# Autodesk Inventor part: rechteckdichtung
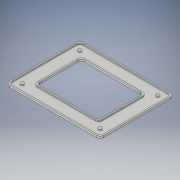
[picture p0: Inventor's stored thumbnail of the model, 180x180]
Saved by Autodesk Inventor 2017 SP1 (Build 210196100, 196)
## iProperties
Part Number: rechteckdichtung
Material: Generisch
Document SubType Name: Modeling
Designer: haesner
Density: 1 g/cm^3
Appearance: Vorgabe
Part Number: rechteckdichtung_3D-Druck
Author: haesner
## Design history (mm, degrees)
sketch "Skizze1"
  geometry: L1 (-41, 33)-(41, 33); L2 (46, 28)-(46, -28); L3 (41, -33)-(-41, -33); L4 (-46, -28)-(-46, 28); L5 (-64.5, 54.5)-(64.5, 54.5); L6 (69.5, 49.5)-(69.5, -49.5); L7 (64.5, -54.5)-(-64.5, -54.5); L8 (-69.5, -49.5)-(-69.5, 49.5); L9 (-98.75, 0)-(98.75, 0) reference; L10 (0, -77.75)-(0, 77.75) reference; A1 r 5 centre (-64.5, 49.5) between (-64.5, 54.5) and (-69.5, 49.5); A2 r 5 centre (64.5, 49.5) between (69.5, 49.5) and (64.5, 54.5); A3 r 5 centre (64.5, -49.5) between (64.5, -54.5) and (69.5, -49.5); A4 r 5 centre (-64.5, -49.5) between (-69.5, -49.5) and (-64.5, -54.5); A5 r 5 centre (-41, 28) between (-41, 33) and (-46, 28); A6 r 5 centre (41, 28) between (46, 28) and (41, 33); A7 r 5 centre (41, -28) between (41, -33) and (46, -28); A8 r 5 centre (-41, -28) between (-46, -28) and (-41, -33); 10 further points
  constraints: 16 end point, 16 point on circle, 16 point on line, 16 tangent, 8 centre point, 6 equal radius, 4 parallel, 2 horizontal, 2 perpendicular, 1 coincident, 4 other
  dimensions: "d0" = 92 distance of point (-46, 33) point (46, 33); "d1" = 66 distance of point (-46, -33) point (-46, 33); "d4" = 139 distance of point (-69.5, 54.5) point (69.5, 54.5); "d5" = 109 distance of point (-69.5, -54.5) point (-69.5, 54.5); "d23" = 5 radius of A1 (derived); "d31" = 5 radius of A5 (derived)
extrude "Extrusion1" new body sketch "Skizze1" distance "d6" = 3; taper "d7" = 0 deg
sketch "Skizze2"
  geometry: L1 (-62.5, 52.5)-(62.5, 52.5); L2 (67.5, 47.5)-(67.5, -47.5); L3 (62.5, -52.5)-(-62.5, -52.5); L4 (-67.5, -47.5)-(-67.5, 47.5); L5 (-43, 35)-(43, 35); L6 (48, 30)-(48, -30); L7 (43, -35)-(-43, -35); L8 (-48, -30)-(-48, 30); L9 (-69.5, 49.5)-(-69.5, -49.5) reference; L10 (64.5, 54.5)-(-64.5, 54.5) reference; L11 (69.705, 9.963)-(184.705, 9.963); L12 (184.705, 9.963)-(184.705, -75.037); L13 (184.705, -75.037)-(69.705, -75.037); L14 (69.705, -75.037)-(69.705, 9.963); L15 (-41, 33)-(41, 33) reference; L16 (-46, -28)-(-46, 28) reference; L17 (-57.5, 42.5)-(57.5, 42.5); L18 (57.5, 42.5)-(57.5, -42.5); L19 (57.5, -42.5)-(-57.5, -42.5); L20 (-57.5, -42.5)-(-57.5, 42.5); C1 r 2.5 at (-57.5, 42.5); C2 r 2.5 at (57.5, 42.5); C3 r 2.5 at (57.5, -42.5); C4 r 2.5 at (-57.5, -42.5); A1 r 5 centre (62.5, 47.5) between (67.5, 47.5) and (62.5, 52.5); A2 r 5 centre (-62.5, 47.5) between (-62.5, 52.5) and (-67.5, 47.5); A3 r 5 centre (-62.5, -47.5) between (-67.5, -47.5) and (-62.5, -52.5); A4 r 5 centre (62.5, -47.5) between (62.5, -52.5) and (67.5, -47.5); A5 r 5 centre (-43, 30) between (-43, 35) and (-48, 30); A6 r 5 centre (43, 30) between (48, 30) and (43, 35); A7 r 5 centre (43, -30) between (43, -35) and (48, -30); A8 r 5 centre (-43, -30) between (-48, -30) and (-43, -35); 14 further points
  constraints: 32 end point, 16 point on circle, 16 tangent, 14 point on line, 12 centre point, 9 equal radius, 8 parallel, 4 coincident, 4 horizontal, 4 perpendicular
  dimensions: "d8" = 2 distance between parallel lines of L9 L4; "d9" = 2 distance between parallel lines of L10 L1 (= d8); "d14" = 135 distance of point (-67.5, 52.5) point (67.5, 52.5); "d15" = 105 distance of point (-67.5, -52.5) point (-67.5, 52.5); "d16" = 85 distance of L11.end L12.end; "d17" = 115 distance of L11.start L11.end; "d18" = 5 radius of A1; "d19" = 2 distance between parallel lines of L15 L5; "d20" = 2 distance between parallel lines of L16 L8 (= d19); "d21" = 96 distance of point (-48, 35) point (48, 35); "d22" = 70 distance of point (-48, -35) point (-48, 35); "d24" = 57.5 distance from line of L18 point (0, 0); "d25" = 42.5 distance from line of L17 point (0, 0); "d26" = 85 distance of L17.end L18.end; "d27" = 115 distance of L18.end L19.end; "d28" = 5 diameter of C1; "d32" = 5 radius of A5 (derived)
extrude "Extrusion2" cut sketch "Skizze2" distance "d29" = 2; taper "d30" = 0 deg
node "Volumenkörper1"
